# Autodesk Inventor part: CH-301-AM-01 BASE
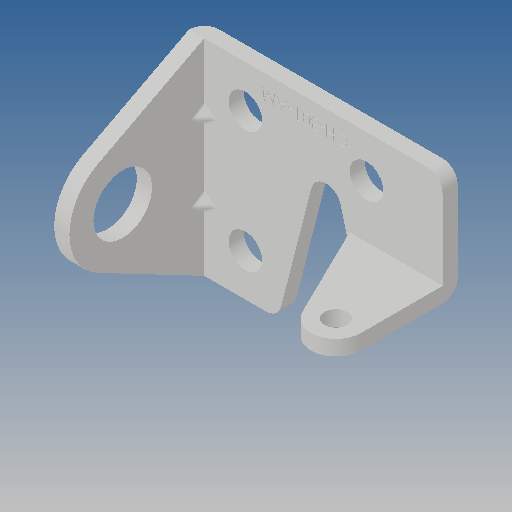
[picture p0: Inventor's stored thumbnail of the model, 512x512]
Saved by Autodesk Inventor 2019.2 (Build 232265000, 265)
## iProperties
Created: 2012-09
Part Number: CH-301-AM-01 BASE
Material: Ogólny
Document SubType Name: Modeling
Designer: CADENGINEERING4
Density: 1 g/cm^3
Appearance: Domyślna
Author: CADENGINEERING4
Revision Number: ÈÎºÎ
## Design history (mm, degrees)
feature "ÇÐ³ý-À­Éì8"
node "Bryła1"
